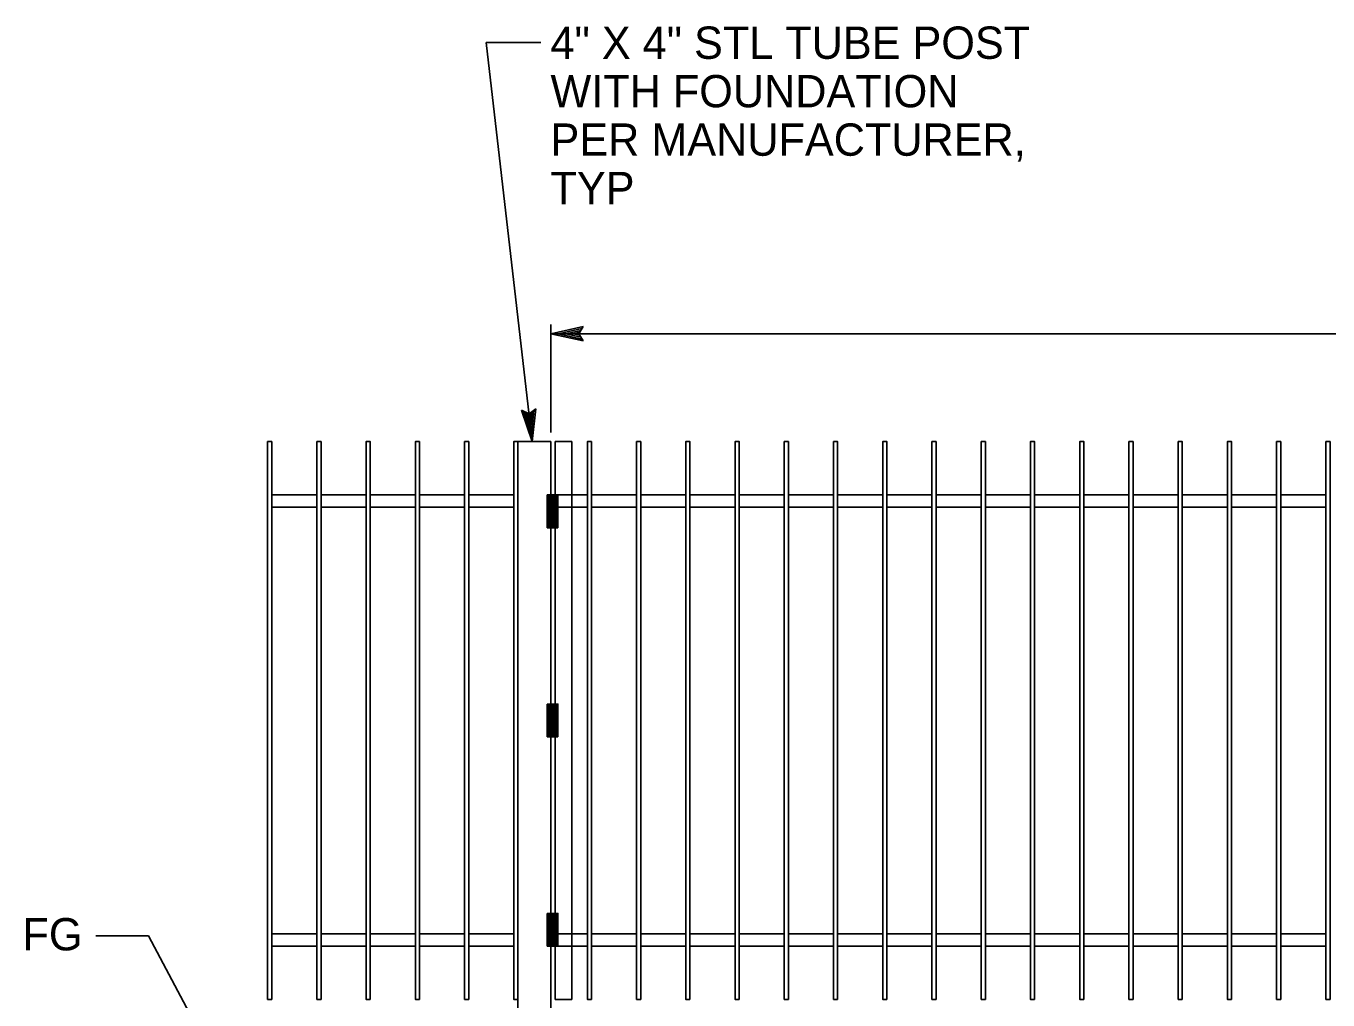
# Model space of a CAD drawing. Extents: x -123486 to -116575, y -107066 to -101122.
# Drawn here: x -118898.2 to -118656.4, y -103051.7 to -102870.8 of the extents above; entities that cross this region are included whole.
import ezdxf

# ---------------------------------------------------------------- set-up
doc = ezdxf.new("R2010")
doc.units = 0
doc.layers.add('G-MARK', color=7, linetype='Continuous')
doc.layers.add('Misc CnstDet(22)', color=7, linetype='Continuous')

msp = doc.modelspace()

# ---------------------------------------------------------------- linework, layer by layer
at = {"layer": 'G-MARK'}
for p, q in [((-118802.55, -102873.86), (-118812.69, -102873.86)), ((-118812.69, -102873.86), (-118804.14, -102947.98)), ((-118800.69, -102946.27), (-118800.69, -102926.23)), ((-118800.69, -102927.94), (-118794.69, -102926.61)), ((-118800.69, -102927.94), (-118459.12, -102927.94)), ((-118794.69, -102929.28), (-118800.69, -102927.94)), ((-118800.69, -102927.94), (-118800.69, -102927.94)), ((-118800.69, -102927.94), (-118456.45, -102927.94)), ((-118794.91, -102928.93), (-118799.31, -102927.94)), ((-118799.3, -102927.94), (-118794.92, -102926.97)), ((-118797.93, -102927.94), (-118795.1, -102927.32)), ((-118795.14, -102928.57), (-118797.93, -102927.94)), ((-118796.55, -102927.95), (-118795.34, -102927.68)), ((-118795.32, -102928.22), (-118796.55, -102927.95)), ((-118794.69, -102926.61), (-118795.49, -102927.94)), ((-118795.49, -102927.94), (-118794.69, -102929.28)), ((-118794.69, -102926.61), (-118794.69, -102926.61)), ((-118794.69, -102929.28), (-118794.69, -102929.28)), ((-118804.14, -102947.98), (-118806.15, -102942.17)), ((-118806.15, -102942.17), (-118806.15, -102942.17)), ((-118806.15, -102942.17), (-118804.74, -102942.82)), ((-118804.31, -102946.6), (-118805.77, -102942.37)), ((-118804.46, -102945.24), (-118805.4, -102942.5)), ((-118804.61, -102943.86), (-118805.02, -102942.69)), ((-118804.74, -102942.82), (-118803.5, -102941.87)), ((-118804.48, -102942.61), (-118804.61, -102943.86)), ((-118804.16, -102942.4), (-118804.46, -102945.24)), ((-118803.83, -102942.12), (-118804.3, -102946.61)), ((-118803.5, -102941.87), (-118804.14, -102947.98)), ((-118803.5, -102941.87), (-118803.5, -102941.87)), ((-118804.14, -102947.98), (-118804.14, -102947.98)), ((-118875.41, -103039.76), (-118885.2, -103039.76)), ((-118865.89, -103057.71), (-118875.41, -103039.76))]:
    msp.add_line(p, q, dxfattribs=at)
at = {"layer": 'Misc CnstDet(22)'}
for p, q in [((-118853.29, -102947.98), (-118853.29, -102947.98)), ((-118843.76, -102947.98), (-118843.76, -102947.98)), ((-118834.62, -102947.98), (-118834.62, -102947.98)), ((-118800.72, -102947.98), (-118807.57, -102947.98)), ((-118807.19, -102947.98), (-118807.19, -102947.98)), ((-118800.72, -102947.98), (-118800.72, -103101.22)), ((-118799.92, -102947.98), (-118799.92, -103007.42)), ((-118799.92, -102947.98), (-118796.77, -102947.98)), ((-118796.77, -102947.98), (-118796.77, -103007.42)), ((-118852.53, -102957.89), (-118844.15, -102957.89)), ((-118843.38, -102957.89), (-118835, -102957.89)), ((-118834.24, -102957.89), (-118825.86, -102957.89)), ((-118825.1, -102957.89), (-118816.71, -102957.89)), ((-118815.95, -102957.89), (-118807.57, -102957.89)), ((-118801.35, -102957.89), (-118801.35, -102963.99)), ((-118800.75, -102957.89), (-118801.35, -102957.89)), ((-118801.15, -102957.89), (-118801.15, -102963.99)), ((-118800.95, -102957.89), (-118800.95, -102963.99)), ((-118800.75, -102957.89), (-118800.75, -102963.99)), ((-118800.72, -102957.89), (-118793.91, -102957.89)), ((-118793.15, -102957.89), (-118784.77, -102957.89)), ((-118784.01, -102957.89), (-118775.63, -102957.89)), ((-118774.86, -102957.89), (-118766.48, -102957.89)), ((-118765.72, -102957.89), (-118757.34, -102957.89)), ((-118756.58, -102957.89), (-118748.19, -102957.89)), ((-118747.43, -102957.89), (-118739.05, -102957.89)), ((-118738.29, -102957.89), (-118729.91, -102957.89)), ((-118729.14, -102957.89), (-118720.76, -102957.89)), ((-118720, -102957.89), (-118711.62, -102957.89)), ((-118710.86, -102957.89), (-118702.47, -102957.89)), ((-118701.71, -102957.89), (-118693.33, -102957.89)), ((-118692.57, -102957.89), (-118684.19, -102957.89)), ((-118683.42, -102957.89), (-118675.04, -102957.89)), ((-118674.28, -102957.89), (-118665.9, -102957.89)), ((-118665.14, -102957.89), (-118656.75, -102957.89)), ((-118852.53, -102960.17), (-118844.15, -102960.17)), ((-118843.38, -102960.17), (-118835, -102960.17)), ((-118834.24, -102960.17), (-118825.86, -102960.17)), ((-118825.1, -102960.17), (-118816.71, -102960.17)), ((-118815.95, -102960.17), (-118807.57, -102960.17)), ((-118806.81, -102960.17), (-118806.81, -103101.22)), ((-118800.72, -102960.17), (-118793.91, -102960.17)), ((-118793.15, -102960.17), (-118784.77, -102960.17)), ((-118784.01, -102960.17), (-118775.63, -102960.17)), ((-118774.86, -102960.17), (-118766.48, -102960.17)), ((-118765.72, -102960.17), (-118757.34, -102960.17)), ((-118756.58, -102960.17), (-118748.19, -102960.17)), ((-118747.43, -102960.17), (-118739.05, -102960.17)), ((-118738.29, -102960.17), (-118729.91, -102960.17)), ((-118729.14, -102960.17), (-118720.76, -102960.17)), ((-118720, -102960.17), (-118711.62, -102960.17)), ((-118710.86, -102960.17), (-118702.47, -102960.17)), ((-118701.71, -102960.17), (-118693.33, -102960.17)), ((-118692.57, -102960.17), (-118684.19, -102960.17)), ((-118683.42, -102960.17), (-118675.04, -102960.17)), ((-118674.28, -102960.17), (-118665.9, -102960.17)), ((-118665.14, -102960.17), (-118656.75, -102960.17)), ((-118800.75, -102963.99), (-118801.35, -102963.99)), ((-118801.35, -102996.75), (-118801.35, -103002.85)), ((-118800.75, -102996.75), (-118801.35, -102996.75)), ((-118801.15, -102996.75), (-118801.15, -103002.85)), ((-118800.95, -102996.75), (-118800.95, -103002.85)), ((-118800.75, -102996.75), (-118800.75, -103002.85)), ((-118800.75, -103002.85), (-118801.35, -103002.85)), ((-118799.92, -103007.42), (-118799.92, -103051.61)), ((-118801.35, -103035.61), (-118801.35, -103041.71)), ((-118800.75, -103035.61), (-118801.35, -103035.61)), ((-118801.15, -103035.61), (-118801.15, -103041.71)), ((-118800.95, -103035.61), (-118800.95, -103041.71)), ((-118800.75, -103035.61), (-118800.75, -103041.71)), ((-118852.53, -103051.61), (-118852.53, -103039.42)), ((-118852.53, -103039.42), (-118844.15, -103039.42)), ((-118843.38, -103039.42), (-118835, -103039.42)), ((-118834.24, -103039.42), (-118825.86, -103039.42)), ((-118825.1, -103039.42), (-118816.71, -103039.42)), ((-118815.95, -103039.42), (-118807.57, -103039.42)), ((-118800.72, -103039.42), (-118793.91, -103039.42)), ((-118793.15, -103039.42), (-118784.77, -103039.42)), ((-118784.01, -103039.42), (-118775.63, -103039.42)), ((-118774.86, -103039.42), (-118766.48, -103039.42)), ((-118765.72, -103039.42), (-118757.34, -103039.42)), ((-118756.58, -103039.42), (-118748.19, -103039.42)), ((-118747.43, -103039.42), (-118739.05, -103039.42)), ((-118738.29, -103039.42), (-118729.91, -103039.42)), ((-118729.14, -103039.42), (-118720.76, -103039.42)), ((-118720, -103039.42), (-118711.62, -103039.42)), ((-118710.86, -103039.42), (-118702.47, -103039.42)), ((-118701.71, -103039.42), (-118693.33, -103039.42)), ((-118692.57, -103039.42), (-118684.19, -103039.42)), ((-118683.42, -103039.42), (-118675.04, -103039.42)), ((-118674.28, -103039.42), (-118665.9, -103039.42)), ((-118665.14, -103039.42), (-118656.75, -103039.42)), ((-118852.53, -103041.71), (-118844.15, -103041.71)), ((-118843.38, -103041.71), (-118835, -103041.71)), ((-118834.24, -103041.71), (-118825.86, -103041.71)), ((-118825.1, -103041.71), (-118816.71, -103041.71)), ((-118815.95, -103041.71), (-118807.57, -103041.71)), ((-118800.75, -103041.71), (-118801.35, -103041.71)), ((-118800.72, -103041.71), (-118793.91, -103041.71)), ((-118793.15, -103041.71), (-118784.77, -103041.71)), ((-118784.01, -103041.71), (-118775.63, -103041.71)), ((-118774.86, -103041.71), (-118766.48, -103041.71)), ((-118765.72, -103041.71), (-118757.34, -103041.71)), ((-118756.58, -103041.71), (-118748.19, -103041.71)), ((-118747.43, -103041.71), (-118739.05, -103041.71)), ((-118738.29, -103041.71), (-118729.91, -103041.71)), ((-118729.14, -103041.71), (-118720.76, -103041.71)), ((-118720, -103041.71), (-118711.62, -103041.71)), ((-118710.86, -103041.71), (-118702.47, -103041.71)), ((-118701.71, -103041.71), (-118693.33, -103041.71)), ((-118692.57, -103041.71), (-118684.19, -103041.71)), ((-118683.42, -103041.71), (-118675.04, -103041.71)), ((-118674.28, -103041.71), (-118665.9, -103041.71)), ((-118665.14, -103041.71), (-118656.75, -103041.71)), ((-118853.29, -103051.61), (-118853.29, -103051.61)), ((-118796.77, -103051.61), (-118799.92, -103051.61))]:
    msp.add_line(p, q, dxfattribs=at)
for points in [[(-118852.53, -103051.61), (-118853.29, -103051.61), (-118853.29, -102947.98), (-118852.53, -102947.98)], [(-118843.38, -103051.61), (-118844.15, -103051.61), (-118844.15, -102947.98), (-118843.38, -102947.98)], [(-118834.24, -103051.61), (-118835, -103051.61), (-118835, -102947.98), (-118834.24, -102947.98)], [(-118825.1, -103051.61), (-118825.86, -103051.61), (-118825.86, -102947.98), (-118825.1, -102947.98)], [(-118815.95, -103051.61), (-118816.71, -103051.61), (-118816.71, -102947.98), (-118815.95, -102947.98)], [(-118806.81, -103051.61), (-118807.57, -103051.61), (-118807.57, -102947.98), (-118806.81, -102947.98)], [(-118793.15, -103051.61), (-118793.91, -103051.61), (-118793.91, -102947.98), (-118793.15, -102947.98)], [(-118784.01, -103051.61), (-118784.77, -103051.61), (-118784.77, -102947.98), (-118784.01, -102947.98)], [(-118774.86, -103051.61), (-118775.63, -103051.61), (-118775.63, -102947.98), (-118774.86, -102947.98)], [(-118765.72, -103051.61), (-118766.48, -103051.61), (-118766.48, -102947.98), (-118765.72, -102947.98)], [(-118756.58, -103051.61), (-118757.34, -103051.61), (-118757.34, -102947.98), (-118756.58, -102947.98)], [(-118747.43, -103051.61), (-118748.19, -103051.61), (-118748.19, -102947.98), (-118747.43, -102947.98)], [(-118738.29, -103051.61), (-118739.05, -103051.61), (-118739.05, -102947.98), (-118738.29, -102947.98)], [(-118729.14, -103051.61), (-118729.91, -103051.61), (-118729.91, -102947.98), (-118729.14, -102947.98)], [(-118720, -103051.61), (-118720.76, -103051.61), (-118720.76, -102947.98), (-118720, -102947.98)], [(-118710.86, -103051.61), (-118711.62, -103051.61), (-118711.62, -102947.98), (-118710.86, -102947.98)], [(-118701.71, -103051.61), (-118702.47, -103051.61), (-118702.47, -102947.98), (-118701.71, -102947.98)], [(-118692.57, -103051.61), (-118693.33, -103051.61), (-118693.33, -102947.98), (-118692.57, -102947.98)], [(-118683.42, -103051.61), (-118684.19, -103051.61), (-118684.19, -102947.98), (-118683.42, -102947.98)], [(-118674.28, -103051.61), (-118675.04, -103051.61), (-118675.04, -102947.98), (-118674.28, -102947.98)], [(-118665.14, -103051.61), (-118665.9, -103051.61), (-118665.9, -102947.98), (-118665.14, -102947.98)], [(-118655.99, -103051.61), (-118656.75, -103051.61), (-118656.75, -102947.98), (-118655.99, -102947.98)], [(-118799.38, -102963.99), (-118800.75, -102963.99), (-118800.75, -102957.89), (-118799.38, -102957.89)], [(-118799.58, -102963.79), (-118800.55, -102963.79), (-118800.55, -102958.09), (-118799.58, -102958.09)], [(-118799.78, -102963.59), (-118800.35, -102963.59), (-118800.35, -102958.29), (-118799.78, -102958.29)], [(-118799.98, -102963.39), (-118800.15, -102963.39), (-118800.15, -102958.49), (-118799.98, -102958.49)], [(-118799.38, -103002.85), (-118800.75, -103002.85), (-118800.75, -102996.75), (-118799.38, -102996.75)], [(-118799.58, -103002.65), (-118800.55, -103002.65), (-118800.55, -102996.95), (-118799.58, -102996.95)], [(-118799.78, -103002.45), (-118800.35, -103002.45), (-118800.35, -102997.15), (-118799.78, -102997.15)], [(-118799.98, -103002.25), (-118800.15, -103002.25), (-118800.15, -102997.35), (-118799.98, -102997.35)], [(-118799.38, -103041.71), (-118800.75, -103041.71), (-118800.75, -103035.61), (-118799.38, -103035.61)], [(-118799.58, -103041.51), (-118800.55, -103041.51), (-118800.55, -103035.81), (-118799.58, -103035.81)], [(-118799.78, -103041.31), (-118800.35, -103041.31), (-118800.35, -103036.01), (-118799.78, -103036.01)], [(-118799.98, -103041.11), (-118800.15, -103041.11), (-118800.15, -103036.21), (-118799.98, -103036.21)]]:
    msp.add_lwpolyline(points, close=True, dxfattribs=at)
msp.add_lwpolyline([(-118796.77, -103007.42), (-118796.77, -103051.61)], dxfattribs=at)

# ---------------------------------------------------------------- texts
for s, p in [('4" X 4" STL TUBE POST ', (-118800.76, -102876.89)), ('WITH FOUNDATION', (-118800.76, -102885.89)), ('PER MANUFACTURER,', (-118800.76, -102894.89)), ('TYP', (-118800.76, -102903.89)), ('FG', (-118898.82, -103042.49))]:
    msp.add_text(s, height=6, dxfattribs=at).set_placement(p)

doc.saveas('drawing.dxf')
